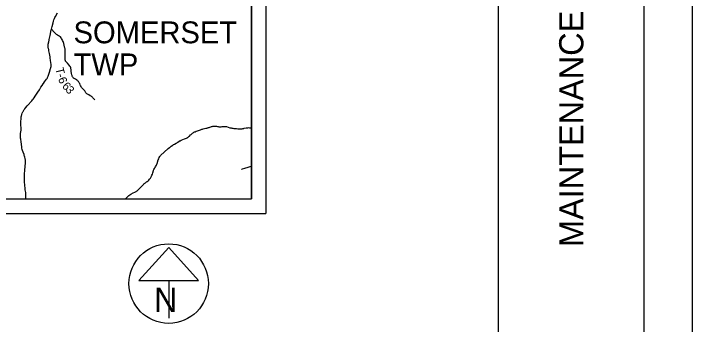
# Model space of a CAD drawing. Extents: x 0 to 191, y 0 to 55.
# Drawn here: x 27 to 34, y 8.48 to 11.68 of the extents above; entities that cross this region are included whole.
import ezdxf

# ---------------------------------------------------------------- set-up
doc = ezdxf.new("R2010")
doc.units = 0
for name, color, linetype in [('GM_X_State_Route', 7, 'Continuous'), ('GM_X_Township_Road', 7, 'Continuous'), ('GM_X_Township_Road_Text', 7, 'Continuous'), ('GM_X_Township_Text', 7, 'Continuous'), ('SH_Border', 7, 'Continuous'), ('SH_Cut_Line', 7, 'Continuous'), ('SH_Data', 7, 'Continuous'), ('SH_Masking', 7, 'Continuous'), ('SH_Text', 7, 'Continuous')]:
    doc.layers.add(name, color=color, linetype=linetype)

msp = doc.modelspace()

# ---------------------------------------------------------------- linework, layer by layer
at = {"layer": 'GM_X_State_Route'}
msp.add_lwpolyline([(27.1234, 9.7697), (27.1226, 9.7762), (27.1221, 9.7839), (27.122, 9.7873), (27.1231, 9.8157), (27.1227, 9.8233), (27.122, 9.8295), (27.1212, 9.8347), (27.1153, 9.8614), (27.114, 9.8687), (27.1134, 9.8744), (27.1111, 9.9102), (27.1094, 9.9434), (27.1078, 9.9793), (27.108, 10.0041), (27.1087, 10.0253), (27.111, 10.0604), (27.1139, 10.1051), (27.1167, 10.1353), (27.1175, 10.1475), (27.1177, 10.1542), (27.1173, 10.165), (27.1166, 10.1713), (27.1155, 10.1777), (27.1139, 10.1841), (27.1112, 10.1971), (27.1084, 10.2081), (27.1056, 10.2174), (27.1031, 10.2248), (27.0948, 10.2488), (27.0877, 10.2683), (27.0846, 10.2792), (27.0815, 10.292), (27.0792, 10.3055), (27.0721, 10.356), (27.0685, 10.3836), (27.067, 10.3958), (27.0662, 10.4076), (27.0681, 10.4419), (27.0719, 10.4772), (27.0725, 10.4893), (27.0724, 10.5026), (27.0711, 10.5257), (27.0707, 10.5401), (27.0713, 10.5703), (27.0723, 10.5894), (27.0735, 10.605), (27.0747, 10.6146), (27.0765, 10.624), (27.0776, 10.6284), (27.0789, 10.6335), (27.0805, 10.6387), (27.0853, 10.652), (27.0878, 10.6578), (27.0909, 10.6645), (27.0934, 10.6694), (27.0978, 10.6773), (27.1024, 10.6842), (27.1057, 10.6888), (27.1122, 10.698), (27.1212, 10.7101), (27.1359, 10.7283), (27.1444, 10.7377), (27.1768, 10.7709), (27.1832, 10.7779), (27.1915, 10.7877), (27.197, 10.7945), (27.2074, 10.8083), (27.2088, 10.8104), (27.2194, 10.826), (27.2459, 10.8671), (27.2622, 10.8936), (27.277, 10.9181), (27.2888, 10.9374), (27.2993, 10.9537), (27.3024, 10.9583), (27.3135, 10.974), (27.3363, 11.0036), (27.3411, 11.0103), (27.3441, 11.015), (27.3468, 11.0196), (27.3491, 11.0245), (27.3524, 11.033), (27.3654, 11.0745), (27.3773, 11.1125), (27.3789, 11.1178), (27.3803, 11.1236), (27.3821, 11.1341), (27.3826, 11.1395), (27.3829, 11.1464), (27.3828, 11.1533), (27.3825, 11.1568), (27.3803, 11.1717), (27.3765, 11.1985), (27.3735, 11.2176), (27.3714, 11.2315), (27.3682, 11.2506), (27.3654, 11.2649), (27.3596, 11.2947), (27.3574, 11.3071), (27.356, 11.315), (27.3533, 11.332), (27.3524, 11.341), (27.3522, 11.3495), (27.3527, 11.3579), (27.3534, 11.3642), (27.3579, 11.3878), (27.3615, 11.4054), (27.3625, 11.4106), (27.3654, 11.424), (27.3718, 11.4535), (27.3842, 11.5115), (27.3854, 11.5164), (27.392, 11.5441), (27.4026, 11.5834), (27.4074, 11.6001), (27.411, 11.6117), (27.4142, 11.6203), (27.4167, 11.6264), (27.4216, 11.637), (27.4278, 11.6487), (27.4479, 11.6844)], dxfattribs=at)
at = {"layer": 'GM_X_Township_Road'}
for points in [[(27.8327, 10.7896), (27.821, 10.8035), (27.8147, 10.8101), (27.8083, 10.816), (27.8029, 10.8204), (27.7948, 10.8262), (27.787, 10.831), (27.7718, 10.8395), (27.7575, 10.8481), (27.7507, 10.8525), (27.7465, 10.8554), (27.7439, 10.8578), (27.7415, 10.8604), (27.74, 10.863), (27.7382, 10.8668), (27.7329, 10.876), (27.729, 10.8815), (27.7241, 10.8876), (27.719, 10.8934), (27.7132, 10.8989), (27.7079, 10.9044), (27.6969, 10.9176), (27.6941, 10.922), (27.6921, 10.9257), (27.6869, 10.9359), (27.6829, 10.9445), (27.6777, 10.9574), (27.6736, 10.9659), (27.6693, 10.9725), (27.6645, 10.9788), (27.661, 10.9827), (27.6563, 10.9866), (27.6507, 10.9905), (27.6438, 10.9945), (27.6328, 11.0004), (27.6258, 11.0044), (27.6196, 11.0083), (27.6136, 11.0128), (27.6088, 11.0176), (27.6054, 11.0225), (27.6029, 11.0272), (27.6009, 11.0316), (27.5992, 11.0356), (27.5981, 11.0395), (27.5966, 11.0453), (27.5933, 11.0601), (27.5919, 11.0687), (27.5912, 11.0736), (27.5904, 11.0808), (27.5884, 11.1004), (27.587, 11.1099), (27.5857, 11.1169), (27.5845, 11.121), (27.583, 11.1255), (27.5809, 11.1301), (27.577, 11.1359), (27.5672, 11.1477), (27.5505, 11.1667), (27.535, 11.185), (27.5322, 11.1888), (27.5306, 11.1917), (27.5294, 11.1942), (27.5288, 11.1974), (27.5286, 11.2014), (27.5284, 11.2057), (27.5286, 11.277), (27.5283, 11.2982), (27.5279, 11.3092), (27.5271, 11.3152), (27.5255, 11.3223), (27.518, 11.3522), (27.5125, 11.3706), (27.5058, 11.3891), (27.5009, 11.4009), (27.4967, 11.4095), (27.491, 11.4206), (27.4876, 11.4262), (27.4853, 11.4293), (27.4784, 11.437), (27.4729, 11.4418), (27.4683, 11.4451), (27.4597, 11.4496), (27.4491, 11.4541), (27.4434, 11.4572), (27.4386, 11.4605), (27.4307, 11.4675), (27.42, 11.4783), (27.4125, 11.4864), (27.3854, 11.5164)], [(28.1481, 9.7697), (28.1527, 9.7738), (28.1784, 9.7978), (28.1855, 9.8038), (28.1951, 9.8108), (28.2052, 9.817), (28.2309, 9.8304), (28.2472, 9.8384), (28.2541, 9.842), (28.259, 9.8448), (28.2653, 9.849), (28.2694, 9.8522), (28.2745, 9.8566), (28.2806, 9.8628), (28.2871, 9.8697), (28.2943, 9.8769), (28.3065, 9.8875), (28.3158, 9.8963), (28.3386, 9.9203), (28.3444, 9.9259), (28.3557, 9.9356), (28.3658, 9.9431), (28.3739, 9.9484), (28.3829, 9.9554), (28.3903, 9.9622), (28.3983, 9.9712), (28.4045, 9.9791), (28.4073, 9.9831), (28.4121, 9.9902), (28.4146, 9.9945), (28.4188, 10.0025), (28.4231, 10.0127), (28.4274, 10.0241), (28.4309, 10.0357), (28.4342, 10.047), (28.4358, 10.0527), (28.4376, 10.0585), (28.44, 10.0647), (28.4431, 10.0716), (28.448, 10.0813), (28.452, 10.0884), (28.4588, 10.0988), (28.463, 10.1057), (28.4693, 10.1177), (28.4737, 10.1277), (28.4761, 10.1338), (28.4883, 10.1695), (28.493, 10.182), (28.4984, 10.1943), (28.5045, 10.2062), (28.5072, 10.2105), (28.5109, 10.2154), (28.5145, 10.2194), (28.5496, 10.2502), (28.5912, 10.2872), (28.604, 10.2981), (28.6098, 10.3024), (28.6225, 10.3116), (28.6372, 10.3216), (28.647, 10.3279), (28.6555, 10.3331), (28.6739, 10.3437), (28.685, 10.3502), (28.6912, 10.3542), (28.7046, 10.363), (28.7086, 10.3654), (28.7126, 10.3672), (28.7232, 10.372), (28.7594, 10.386), (28.7682, 10.3898), (28.7784, 10.3941), (28.7853, 10.3972), (28.7898, 10.3997), (28.794, 10.4023), (28.7984, 10.4052), (28.8043, 10.41), (28.8112, 10.416), (28.8216, 10.4273), (28.8283, 10.4337), (28.8353, 10.4399), (28.8409, 10.4444), (28.8494, 10.4503), (28.856, 10.4544), (28.8634, 10.4584), (28.8681, 10.4607), (28.8787, 10.4652), (28.8938, 10.4707), (28.9245, 10.4817), (28.9368, 10.4858), (28.9436, 10.4879), (28.9527, 10.4902), (28.9668, 10.4933), (28.9798, 10.4961), (28.9917, 10.4989), (28.9975, 10.5004), (29.0076, 10.5034), (29.0136, 10.5053), (29.039, 10.5135), (29.0446, 10.5151), (29.0504, 10.5163), (29.0564, 10.5173), (29.0632, 10.5179), (29.0718, 10.518), (29.0802, 10.5175), (29.0886, 10.5164), (29.1001, 10.5145), (29.1072, 10.5134), (29.114, 10.5125), (29.1201, 10.512), (29.1251, 10.5119), (29.137, 10.5121), (29.1489, 10.5137), (29.1568, 10.5148), (29.1618, 10.5154), (29.1672, 10.5157), (29.1733, 10.5154), (29.1788, 10.5151), (29.1851, 10.5143), (29.1912, 10.5131), (29.2083, 10.508), (29.2271, 10.5024), (29.2336, 10.5008), (29.239, 10.4998), (29.2478, 10.4982), (29.2573, 10.4967), (29.2687, 10.4952), (29.286, 10.4934), (29.2971, 10.4923), (29.3102, 10.4913), (29.3199, 10.4909), (29.3328, 10.4907), (29.3402, 10.4908), (29.346, 10.4912), (29.3539, 10.4921), (29.3607, 10.4928), (29.3696, 10.4942), (29.3762, 10.4956), (29.3968, 10.4999), (29.4074, 10.5018), (29.4124, 10.5023), (29.4177, 10.5026), (29.4312, 10.5021), (29.4352, 10.5015), (29.4405, 10.5004), (29.4451, 10.4992), (29.4489, 10.498)], [(29.3455, 10.0751), (29.3511, 10.0763), (29.3565, 10.0779), (29.3808, 10.0853), (29.4146, 10.0956), (29.4478, 10.1057), (29.4489, 10.106)]]:
    msp.add_lwpolyline(points, dxfattribs=at)
at = {"layer": 'GM_X_Township_Text'}
msp.add_lwpolyline([(26.7829, 9.7697), (29.4489, 9.7697), (29.4489, 17.4562), (27.7742, 17.4846), (27.6359, 17.4861), (27.112, 17.4915), (26.9474, 17.4931), (26.8962, 17.4941)], dxfattribs=at)
at = {"layer": 'SH_Border'}
msp.add_line((32, 0.5), (32, 21.5), dxfattribs=at)
msp.add_lwpolyline([(1.5, 21.5), (33.5, 21.5), (33.5, 0.5), (1.5, 0.5)], close=True, dxfattribs=at)
at = {"layer": 'SH_Cut_Line'}
msp.add_lwpolyline([(0, 0), (34, 0), (34, 22), (0, 22)], close=True, dxfattribs=at)
at = {"layer": 'SH_Data'}
for p, q in [((29.5989, 20.1197), (29.5989, 9.6197)), ((29.4489, 19.9697), (29.4489, 9.7697)), ((19.2489, 9.7697), (29.4489, 9.7697)), ((19.0989, 9.6197), (29.5989, 9.6197))]:
    msp.add_line(p, q, dxfattribs=at)
at = {"layer": 'SH_Masking'}
msp.add_circle((28.5958, 8.8957), 0.41, dxfattribs=at)
at = {"layer": 'SH_Text'}
for p, q in [((28.5958, 9.2694), (28.2882, 8.9282)), ((28.9034, 8.9282), (28.5958, 9.2694)), ((28.2882, 8.9282), (28.9034, 8.9282)), ((28.5958, 8.9282), (28.5958, 8.5414))]:
    msp.add_line(p, q, dxfattribs=at)
msp.add_circle((28.5958, 8.8957), 0.41, dxfattribs=at)

# ---------------------------------------------------------------- texts
at = {"layer": 'GM_X_Township_Road_Text'}
for s, rotation, p in [('T', 283.94115, (27.426, 11.1113)), ('6', 289.52941, (27.4528, 11.0069)), ('-', 284.59257, (27.4416, 11.0484)), ('6', 313.14185, (27.4901, 10.925)), ('3', 311.65126, (27.5256, 10.8871))]:
    msp.add_text(s, height=0.0852, rotation=rotation, dxfattribs=at).set_placement(p)
at = {"layer": 'GM_X_Township_Text'}
for s, p in [('SOMERSET', (27.6138, 11.3717)), ('TWP', (27.6138, 11.0417))]:
    msp.add_text(s, height=0.225, rotation=0.00001, dxfattribs=at).set_placement(p)
at = {"layer": 'SH_Data'}
msp.add_text('MAINTENANCE OF TRAFFIC (NOB-147-18.41)', height=0.25, rotation=90, dxfattribs=at).set_placement((32.875, 9.2735))
at = {"layer": 'SH_Text'}
msp.add_text('N', height=0.25, dxfattribs=at).set_placement((28.4445, 8.6043))

doc.saveas('drawing.dxf')
